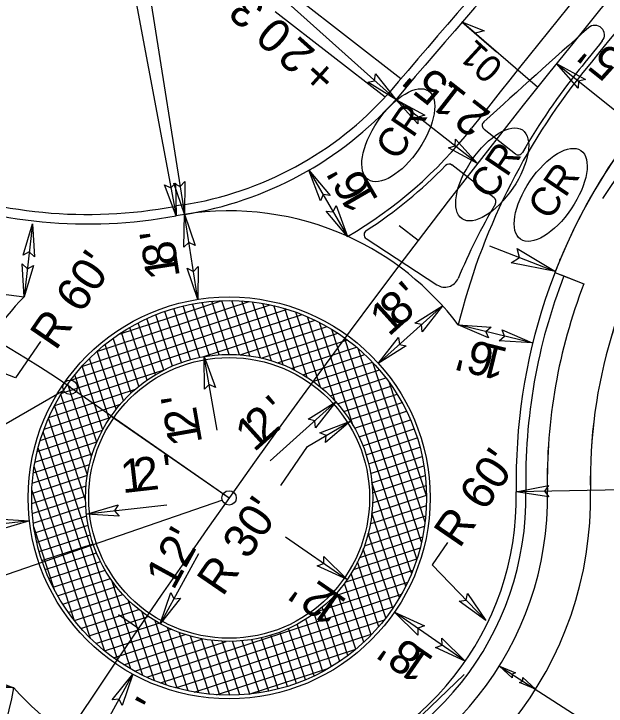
# Model space of a CAD drawing. Extents: x 1975573 to 1977432, y 778300 to 780514.
# Drawn here: x 1976308 to 1976462.7, y 779399.7 to 779580.6 of the extents above; entities that cross this region are included whole.
import ezdxf

# ---------------------------------------------------------------- set-up
doc = ezdxf.new("R2010")
doc.units = 0
for name, color, linetype in [('Default', 7, 'Continuous'), ('Prop Conc 1ft 6in Curb and Gutter', 7, 'Continuous'), ('Prop Conc 2ft 6in Curb and Gutter', 7, 'Continuous'), ('Prop Conc 4in Sidewalk', 7, 'Continuous'), ('Prop Conc 5in Monolithic Keyed In Island', 7, 'Continuous'), ('Prop Conc Curb 8in x 18in', 7, 'Continuous'), ('Prop Conc Drive Radius Type', 7, 'Continuous'), ('Prop Dimension', 7, 'Continuous'), ('Prop Dimension Text', 7, 'Continuous'), ('Prop EOT', 7, 'Continuous'), ('Prop Horizontal Alignment', 7, 'Continuous'), ('Prop Horizontal Alignment Station Label', 7, 'Continuous'), ('Prop Horizontal Alignment Tick Small', 7, 'Continuous'), ('Prop Lane Lines', 7, 'Continuous'), ('Prop Superelevation  Arrow CELL', 7, 'Continuous'), ('Prop Superelevation Label', 7, 'Continuous'), ('Prop Terminator CELL', 7, 'Continuous'), ('Prop WCC CELL', 7, 'Continuous'), ('Typical Terminator CELL', 7, 'Continuous')]:
    doc.layers.add(name, color=color, linetype=linetype)

# ---------------------------------------------------------------- blocks, each defined once
blk = doc.blocks.new('TERMINATOR')
at = {"layer": 'Typical Terminator CELL'}
blk.add_lwpolyline([(-0.4687, 0.0807), (0, 0), (-0.4713, -0.0833), (-0.4114, 0)], close=True, dxfattribs=at)

msp = doc.modelspace()

# ---------------------------------------------------------------- linework, layer by layer
at = {"layer": 'Default'}
for p, q in [((1976329.67, 779492.39), (1976369.49, 779505.41)), ((1976335.46, 779496.92), (1976362.14, 779505.64)), ((1976364.24, 779491.6), (1976359.7, 779505.48)), ((1976366.91, 779491.5), (1976362.28, 779505.64)), ((1976369.63, 779491.2), (1976364.9, 779505.68)), ((1976372.43, 779490.69), (1976367.57, 779505.57)), ((1976325.79, 779488.49), (1976374.92, 779504.56)), ((1976354.17, 779490.24), (1976349.79, 779503.62)), ((1976356.61, 779490.83), (1976352.21, 779504.26)), ((1976359.1, 779491.25), (1976354.67, 779504.79)), ((1976361.64, 779491.51), (1976357.17, 779505.2)), ((1976375.31, 779489.92), (1976370.28, 779505.32)), ((1976378.29, 779488.88), (1976373.04, 779504.92)), ((1976381.38, 779487.44), (1976375.86, 779504.35)), ((1976384.63, 779485.54), (1976378.73, 779503.6)), ((1976320.54, 779481.52), (1976383.28, 779502.03)), ((1976322.86, 779484.91), (1976379.41, 779503.39)), ((1976349.45, 779488.57), (1976345.06, 779501.99)), ((1976351.78, 779489.49), (1976347.41, 779502.86)), ((1976388.09, 779483.03), (1976381.68, 779502.64)), ((1976347.17, 779487.5), (1976342.76, 779501)), ((1976357.63, 779491.02), (1976386.7, 779500.52)), ((1976391.9, 779479.41), (1976384.7, 779501.44)), ((1976342.78, 779484.86), (1976338.26, 779498.67)), ((1976344.95, 779486.26), (1976340.49, 779499.9)), ((1976367.12, 779491.49), (1976389.78, 779498.9)), ((1976396.64, 779472.96), (1976387.81, 779499.97)), ((1976411.87, 779434.42), (1976391.03, 779498.16)), ((1976340.67, 779483.27), (1976336.07, 779497.32)), ((1976372.61, 779490.65), (1976392.58, 779497.18)), ((1976338.62, 779481.49), (1976333.92, 779495.84)), ((1976376.84, 779489.4), (1976395.13, 779495.39)), ((1976413.26, 779438.2), (1976394.39, 779495.93)), ((1976336.64, 779479.49), (1976331.82, 779494.23)), ((1976380.39, 779487.93), (1976397.48, 779493.52)), ((1976414.47, 779442.56), (1976397.94, 779493.13)), ((1976334.74, 779477.26), (1976329.76, 779492.48)), ((1976383.45, 779486.3), (1976399.63, 779491.6)), ((1976332.93, 779474.76), (1976327.76, 779490.58)), ((1976386.11, 779484.54), (1976401.62, 779489.61)), ((1976415.39, 779447.79), (1976401.77, 779489.46)), ((1976318.66, 779478.28), (1976347.77, 779487.79)), ((1976331.22, 779471.93), (1976325.8, 779488.51)), ((1976388.48, 779482.69), (1976403.45, 779487.58)), ((1976329.67, 779468.64), (1976323.9, 779486.27)), ((1976390.59, 779480.75), (1976405.13, 779485.5)), ((1976328.29, 779464.81), (1976322.07, 779483.82)), ((1976415.78, 779454.65), (1976406.13, 779484.15)), ((1976317.14, 779475.15), (1976339.76, 779482.54)), ((1976392.48, 779478.73), (1976406.68, 779483.38)), ((1976327.21, 779460.05), (1976320.31, 779481.16)), ((1976394.16, 779476.66), (1976408.09, 779481.21)), ((1976315.9, 779472.11), (1976335.85, 779478.63)), ((1976395.66, 779474.52), (1976409.38, 779479)), ((1976326.73, 779453.5), (1976318.64, 779478.23)), ((1976396.98, 779472.32), (1976410.55, 779476.75)), ((1976314.9, 779469.15), (1976333.19, 779475.13)), ((1976338.51, 779409.42), (1976317.07, 779474.99)), ((1976398.14, 779470.07), (1976411.6, 779474.47)), ((1976314.11, 779466.26), (1976331.18, 779471.85)), ((1976335.2, 779411.5), (1976315.62, 779471.36)), ((1976399.14, 779467.76), (1976412.53, 779472.14)), ((1976399.98, 779465.41), (1976413.35, 779469.78)), ((1976313.5, 779463.44), (1976329.71, 779468.73)), ((1976313.07, 779460.67), (1976328.59, 779465.74)), ((1976331.72, 779414.09), (1976314.35, 779467.22)), ((1976400.64, 779462.99), (1976414.05, 779467.38)), ((1976401.15, 779460.53), (1976414.63, 779464.94)), ((1976312.8, 779457.95), (1976327.77, 779462.84)), ((1976328, 779417.42), (1976313.32, 779462.34)), ((1976401.5, 779458.01), (1976415.1, 779462.46)), ((1976312.67, 779455.27), (1976327.21, 779460.03)), ((1976401.67, 779455.44), (1976415.45, 779459.94)), ((1976312.68, 779452.65), (1976326.87, 779457.29)), ((1976410.34, 779431.06), (1976401.48, 779458.16)), ((1976401.67, 779452.81), (1976415.68, 779457.39)), ((1976323.87, 779422.02), (1976312.7, 779456.18)), ((1976401.48, 779450.12), (1976415.78, 779454.79)), ((1976312.82, 779450.06), (1976326.74, 779454.61)), ((1976313.08, 779447.52), (1976326.8, 779452)), ((1976401.08, 779447.36), (1976415.74, 779452.15)), ((1976313.47, 779445.01), (1976327.04, 779449.45)), ((1976400.45, 779444.52), (1976415.57, 779449.46)), ((1976408.7, 779428.04), (1976401.48, 779450.11)), ((1976318.6, 779430.08), (1976313.21, 779446.56)), ((1976313.97, 779442.55), (1976327.43, 779446.95)), ((1976399.55, 779441.59), (1976415.25, 779446.73)), ((1976314.59, 779440.12), (1976328, 779444.5)), ((1976398.34, 779438.57), (1976414.77, 779443.94)), ((1976406.97, 779425.29), (1976400.55, 779444.92)), ((1976315.33, 779437.73), (1976328.71, 779442.11)), ((1976396.68, 779435.4), (1976414.11, 779441.09)), ((1976405.16, 779422.77), (1976399.26, 779440.81)), ((1976316.18, 779435.38), (1976329.59, 779439.76)), ((1976317.15, 779433.07), (1976330.63, 779437.47)), ((1976394.53, 779432.06), (1976413.26, 779438.18)), ((1976403.28, 779420.46), (1976397.75, 779437.39)), ((1976318.23, 779430.79), (1976331.82, 779435.23)), ((1976391.52, 779428.45), (1976412.19, 779435.2)), ((1976319.44, 779428.55), (1976333.2, 779433.05)), ((1976401.35, 779418.34), (1976396.1, 779434.4)), ((1976341.69, 779407.74), (1976333.59, 779432.52)), ((1976386.97, 779424.33), (1976410.86, 779432.14)), ((1976399.36, 779416.38), (1976394.32, 779431.77)), ((1976320.77, 779426.36), (1976334.75, 779430.93)), ((1976397.31, 779414.58), (1976392.45, 779429.44)), ((1976322.22, 779424.2), (1976336.5, 779428.87)), ((1976342.74, 779407.24), (1976409.24, 779428.98)), ((1976323.81, 779422.09), (1976338.45, 779426.88)), ((1976344.77, 779406.37), (1976337.87, 779427.47)), ((1976395.23, 779412.92), (1976390.5, 779427.38)), ((1976325.53, 779420.03), (1976340.64, 779424.96)), ((1976347.76, 779405.25), (1976341.54, 779424.29)), ((1976346.29, 779405.77), (1976407.24, 779425.7)), ((1976393.09, 779411.4), (1976388.48, 779425.53)), ((1976327.41, 779418.01), (1976343.1, 779423.14)), ((1976350.33, 779404.46), (1976404.76, 779422.25)), ((1976388.7, 779408.74), (1976384.23, 779422.41)), ((1976390.92, 779410.01), (1976386.39, 779423.88)), ((1976329.45, 779416.04), (1976345.9, 779421.42)), ((1976350.68, 779404.37), (1976344.92, 779421.97)), ((1976386.45, 779407.59), (1976382.02, 779421.12)), ((1976331.66, 779414.14), (1976349.08, 779419.83)), ((1976353.54, 779403.67), (1976348.11, 779420.27)), ((1976356.33, 779403.16), (1976351.16, 779418.99)), ((1976355.06, 779403.38), (1976401.58, 779418.59)), ((1976381.82, 779405.65), (1976377.44, 779419.05)), ((1976384.15, 779406.57), (1976379.76, 779420.01)), ((1976334.06, 779412.29), (1976352.78, 779418.41)), ((1976336.69, 779410.52), (1976357.34, 779417.27)), ((1976359.08, 779402.81), (1976354.1, 779418.03)), ((1976361.77, 779402.61), (1976356.96, 779417.35)), ((1976364.42, 779402.56), (1976359.73, 779416.91)), ((1976372.11, 779403.16), (1976367.66, 779416.8)), ((1976374.6, 779403.61), (1976370.18, 779417.12)), ((1976377.04, 779404.18), (1976372.65, 779417.6)), ((1976379.45, 779404.86), (1976375.07, 779418.25)), ((1976339.56, 779408.83), (1976363.41, 779416.63)), ((1976367.03, 779402.63), (1976362.43, 779416.68)), ((1976369.59, 779402.84), (1976365.07, 779416.65)), ((1976360.92, 779402.66), (1976397.28, 779414.55)), ((1976369.45, 779402.82), (1976390.29, 779409.64))]:
    msp.add_line(p, q, dxfattribs=at)
msp.add_circle((1976364.22, 779454.12), 37.5, dxfattribs=at)
at = {"layer": 'Prop Conc 1ft 6in Curb and Gutter'}
msp.add_circle((1976364.22, 779454.12), 51.56, dxfattribs=at)
at = {"layer": 'Prop Conc 2ft 6in Curb and Gutter'}
for centre, radius, start, end in [((1978239.96, 778006.13), 2403.74, 136.72119, 139.7323), ((1976337.97, 779620.81), 91.25, 278.9494, 318.0674), ((1976327.31, 779650.68), 122.5, 248.3898, 280.6337), ((1976364.22, 779454.12), 77.5, 98.9494, 100.6337), ((1976589.17, 779458.81), 147.5, 158.8164, 181.1936), ((1976364.22, 779454.12), 77.5, 281.7976, 1.1936)]:
    msp.add_arc(centre, radius, start, end, dxfattribs=at)
at = {"layer": 'Prop Conc 4in Sidewalk'}
for p, q in [((1976409.06, 779563.62), (1976380.92, 779585.56)), ((1976376.28, 779581.25), (1976404.98, 779558.88)), ((1976449.31, 779513.01), (1976456.88, 779510.07)), ((1976449.31, 779513.01), (1976456.88, 779510.07)), ((1976449.31, 779513.01), (1976451.64, 779512.11)), ((1976451.64, 779512.11), (1976456.88, 779510.07))]:
    msp.add_line(p, q, dxfattribs=at)
for centre, radius, start, end in [((1976589.17, 779458.81), 150, 142.1787, 158.8164), ((1976589.17, 779458.81), 150, 142.1787, 158.8164), ((1976589.17, 779458.81), 130.63, 145.3825, 181.1936), ((1976589.17, 779458.81), 130.62, 145.3825, 181.1936), ((1976589.17, 779458.81), 141.88, 158.8164, 181.1936), ((1976589.17, 779458.81), 141.87, 158.8164, 181.1936), ((1976589.17, 779458.81), 141.87, 158.8164, 181.1936), ((1976364.22, 779454.12), 83.13, 281.7976, 1.1936), ((1976364.22, 779454.12), 83.12, 281.7976, 1.1936), ((1976364.22, 779454.12), 83.13, 281.7976, 1.1936), ((1976364.22, 779454.12), 94.38, 281.7976, 1.1936), ((1976364.22, 779454.12), 94.38, 281.7976, 1.1936)]:
    msp.add_arc(centre, radius, start, end, dxfattribs=at)
at = {"layer": 'Prop Conc 5in Monolithic Keyed In Island'}
msp.add_line((1976400.03, 779521.91), (1976418.5, 779509.78), dxfattribs=at)
for points in [[(1976430.8, 779550.44), (1976438.98, 779544.02)], [(1976433.43, 779532.56), (1976422.41, 779541.1)], [(1976400.03, 779521.91), (1976418.5, 779509.78)]]:
    msp.add_lwpolyline(points, dxfattribs=at)
for centre, radius, start, end in [((1978056.54, 777773.04), 2410.22, 131.54456, 132.41906), ((1978056.54, 777773.04), 2410.22, 131.54456, 132.41906), ((1976459.73, 779575.08), 2.5, 321.0068, 131.5446), ((1976459.73, 779575.08), 2.5, 321.0068, 131.5446), ((1978303.2, 778082.63), 2369.38, 141.00683, 141.23948), ((1978303.2, 778082.63), 2369.38, 141.00683, 141.23948), ((1976589.17, 779458.81), 171.25, 141.2395, 150.018), ((1976589.17, 779458.81), 171.25, 141.2395, 150.018), ((1976431.57, 779551.42), 1.25, 132.4191, 231.9065), ((1976431.57, 779551.42), 1.25, 132.4191, 231.9065), ((1976439.75, 779545.01), 1.25, 231.9065, 330.018), ((1976439.75, 779545.01), 1.25, 231.9065, 330.018), ((1976337.97, 779620.81), 115, 302.6674, 316.0364), ((1976337.97, 779620.81), 115, 302.6674, 316.0364), ((1976421.64, 779540.11), 1.25, 52.2081, 136.0364), ((1976421.64, 779540.11), 1.25, 52.2081, 136.0364), ((1976432.66, 779531.57), 1.25, 329.792, 52.2081), ((1976432.66, 779531.57), 1.25, 329.792, 52.2081), ((1976580.48, 779445.51), 169.79, 149.792, 157.1435), ((1976580.48, 779445.51), 169.79, 149.792, 157.1435), ((1976400.71, 779522.95), 1.25, 122.6674, 236.722), ((1976400.71, 779522.95), 1.25, 122.6674, 236.722), ((1976420.56, 779512.92), 3.75, 236.722, 337.1435), ((1976420.56, 779512.92), 3.75, 236.722, 337.1435)]:
    msp.add_arc(centre, radius, start, end, dxfattribs=at)
at = {"layer": 'Prop Conc Curb 8in x 18in'}
msp.add_circle((1976364.22, 779454.12), 36.67, dxfattribs=at)
at = {"layer": 'Prop Conc Drive Radius Type'}
for p, q in [((1976475.61, 779553.23), (1976461.7, 779532.36)), ((1976425.61, 779407.97), (1976407.53, 779390.7))]:
    msp.add_line(p, q, dxfattribs=at)
at = {"layer": 'Prop Dimension'}
for p, q in [((1976432.24, 779519.95), (1976449.42, 779513.3)), ((1976450.54, 779516.2), (1976450.68, 779516.56)), ((1976434.79, 779410.19), (1976466.33, 779389.91))]:
    msp.add_line(p, q, dxfattribs=at)
at = {"layer": 'Prop Dimension Text'}
for p, q in [((1976327.31, 779650.68), (1976350.38, 779527.83)), ((1976337.97, 779620.81), (1976352.55, 779528.21)), ((1976337.97, 779620.81), (1976407.71, 779558.17)), ((1976449.69, 779567.6), (1976470.68, 779550.79)), ((1976429.09, 779541.52), (1976407.71, 779558.17)), ((1976385.06, 779539.75), (1976395.11, 779522.46)), ((1976356.05, 779505.98), (1976352.55, 779528.21)), ((1976312.88, 779525.73), (1976310.68, 779506.64)), ((1976403.18, 779489.25), (1976419.92, 779504.34)), ((1976443.35, 779494.59), (1976424.07, 779499.32)), ((1976314.93, 779494.98), (1976308.4, 779485.46)), ((1976361.1, 779471.83), (1976357.73, 779491.05)), ((1976308.4, 779485.46), (1976298.09, 779489.5)), ((1976374.96, 779463.81), (1976392.07, 779479.23)), ((1976333.38, 779475.45), (1976364.22, 779454.12)), ((1976384.66, 779467.52), (1976395.91, 779474.16)), ((1976377.72, 779457.38), (1976384.66, 779467.52)), ((1976589.17, 779458.81), (1976439.2, 779455.68)), ((1976347.97, 779452.26), (1976326.96, 779449.85)), ((1976312.06, 779448.15), (1976289.7, 779445.59)), ((1976378.97, 779443.91), (1976395.06, 779432.79)), ((1976421.25, 779442.45), (1976417.25, 779436.61)), ((1976356.23, 779439.5), (1976346.23, 779421.21)), ((1976417.25, 779436.61), (1976431.23, 779422.07)), ((1976425.9, 779411.46), (1976407.4, 779424.25)), ((1976289.66, 779407.94), (1976308, 779404.47)), ((1976328.24, 779388.31), (1976339.03, 779408.05))]:
    msp.add_line(p, q, dxfattribs=at)
at = {"layer": 'Prop EOT'}
msp.add_circle((1976364.22, 779454.12), 52.5, dxfattribs=at)
for centre, radius, start, end in [((1978239.96, 778006.13), 2401.24, 136.7176, 139.73317), ((1976337.97, 779620.81), 93.75, 278.9494, 318.0674), ((1976589.17, 779458.81), 150, 142.1787, 181.1936), ((1976327.31, 779650.68), 125, 248.3898, 280.6337), ((1976364.22, 779454.12), 75, 98.9494, 100.6337), ((1976364.22, 779454.12), 75, 281.7976, 1.1936)]:
    msp.add_arc(centre, radius, start, end, dxfattribs=at)
at = {"layer": 'Prop Horizontal Alignment'}
msp.add_line((1976322.68, 779483.02), (1976364.22, 779454.12), dxfattribs=at)
msp.add_line((1976322.68, 779483.02), (1976364.22, 779454.12), dxfattribs=at)
for centre, radius, start, end in [((1978303.2, 778082.63), 2375, 135.73946, 152.1381), ((1976179.17, 779276.72), 251.3, 55.1768, 88.8319), ((1976179.17, 779276.72), 251.3, 55.1768, 88.8319), ((1976179.17, 779276.72), 251.3, 55.1768, 88.8319), ((1976179.17, 779276.72), 251.3, 55.1768, 88.8319), ((1976179.17, 779276.72), 251.3, 55.1768, 88.8319)]:
    msp.add_arc(centre, radius, start, end, dxfattribs=at)
at = {"layer": 'Prop Horizontal Alignment Station Label'}
for p, q in [((1976321.01, 779482.16), (1976180.99, 779401.56)), ((1976362.45, 779453.51), (1976212.49, 779401.79))]:
    msp.add_line(p, q, dxfattribs=at)
for centre in [(1976322.68, 779483.02), (1976322.68, 779483.02), (1976364.22, 779454.12)]:
    msp.add_circle(centre, 1.88, dxfattribs=at)
at = {"layer": 'Prop Horizontal Alignment Tick Small'}
for p, q in [((1976413.61, 779521.41), (1976408.64, 779525.2)), ((1976340.54, 779420.01), (1976335.37, 779423.53))]:
    msp.add_line(p, q, dxfattribs=at)
at = {"layer": 'Prop Lane Lines'}
for centre, radius, start, end in [((1978303.2, 778082.63), 2381.88, 135.73946, 141.94983), ((1978303.2, 778082.63), 2368.12, 135.73946, 141.23948), ((1976589.17, 779458.81), 170, 141.2395, 166.2129), ((1976337.97, 779620.81), 113.75, 300.1571, 321.9498), ((1976364.22, 779454.12), 75, 65.6747, 98.9494), ((1976364.22, 779454.12), 75, 37.0615, 65.6747), ((1976327.31, 779650.68), 145, 250.6014, 263.4132), ((1976364.22, 779454.12), 75, 135.5489, 156.1292), ((1976165.52, 779431.37), 145, 330.7648, 349.3113), ((1976364.22, 779454.12), 75, 221.447, 248.5228)]:
    msp.add_arc(centre, radius, start, end, dxfattribs=at)
at = {"layer": 'Prop Superelevation  Arrow CELL'}
msp.add_line((1976424.98, 779578.54), (1976434.06, 779570.69), dxfattribs=at)
msp.add_lwpolyline([(1976424.98, 779578.54), (1976430.83, 779576.13), (1976428.48, 779575.51)], close=True, dxfattribs=at)
at = {"layer": 'Prop Superelevation Label'}
msp.add_line((1976444.77, 779561.44), (1976424.98, 779578.54), dxfattribs=at)
at = {"layer": 'Prop Terminator CELL'}
for points in [[(1976455.37, 779561.19), (1976449.69, 779567.6), (1976457.25, 779563.47), (1976455.47, 779562.97)], [(1976402.4, 779564.88), (1976407.71, 779558.17), (1976400.4, 779562.72), (1976402.2, 779563.11)], [(1976413.48, 779551.84), (1976407.71, 779558.17), (1976415.33, 779554.14), (1976413.55, 779553.62)], [(1976423.33, 779547.85), (1976429.09, 779541.52), (1976421.48, 779545.55), (1976423.25, 779546.07)], [(1976388.05, 779531.73), (1976385.06, 779539.75), (1976390.62, 779533.17), (1976388.79, 779533.35)], [(1976350.25, 779536.39), (1976350.38, 779527.83), (1976347.34, 779535.89), (1976349.01, 779535.11)], [(1976352.67, 779536.77), (1976352.55, 779528.21), (1976349.75, 779536.35), (1976351.4, 779535.52)], [(1976392.13, 779530.49), (1976395.11, 779522.46), (1976389.55, 779529.04), (1976391.39, 779528.86)], [(1976352.43, 779519.64), (1976352.55, 779528.21), (1976355.35, 779520.06), (1976353.7, 779520.89)], [(1976310.47, 779517.52), (1976312.88, 779525.73), (1976313.4, 779517.13), (1976312.03, 779518.37)], [(1976313.09, 779514.86), (1976310.68, 779506.64), (1976310.16, 779515.24), (1976311.53, 779514)], [(1976356.17, 779514.54), (1976356.05, 779505.98), (1976353.25, 779514.13), (1976354.9, 779513.3)], [(1976412.68, 779499.77), (1976419.92, 779504.34), (1976414.62, 779497.55), (1976414.42, 779499.38)], [(1976431.92, 779495.9), (1976424.07, 779499.32), (1976432.66, 779498.75), (1976431.26, 779497.55)], [(1976435.5, 779498.01), (1976443.35, 779494.59), (1976434.75, 779495.15), (1976436.15, 779496.35)], [(1976410.42, 779493.82), (1976403.18, 779489.25), (1976408.48, 779496.05), (1976408.68, 779494.21)], [(1976357.76, 779482.49), (1976357.73, 779491.05), (1976360.67, 779482.96), (1976359.01, 779483.76)], [(1976384.83, 779474.66), (1976392.07, 779479.23), (1976386.77, 779472.44), (1976386.57, 779474.27)], [(1976387.91, 779471.12), (1976395.91, 779474.16), (1976389.37, 779468.56), (1976389.53, 779470.4)], [(1976447.67, 779454.4), (1976439.2, 779455.68), (1976447.65, 779457.36), (1976446.61, 779455.84)], [(1976335.51, 779449.37), (1976326.96, 779449.85), (1976335.22, 779452.31), (1976334.32, 779450.7)], [(1976303.51, 779448.63), (1976312.06, 779448.15), (1976303.8, 779445.69), (1976304.7, 779447.3)], [(1976388.95, 779438.78), (1976395.06, 779432.79), (1976387.23, 779436.38), (1976388.97, 779437)], [(1976351.55, 779427.92), (1976346.23, 779421.21), (1976348.98, 779429.38), (1976349.78, 779427.71)], [(1976426.43, 779429.16), (1976431.23, 779422.07), (1976424.27, 779427.15), (1976426.09, 779427.41)], [(1976413.51, 779418.26), (1976407.4, 779424.25), (1976415.23, 779420.66), (1976413.49, 779420.04)], [(1976419.79, 779417.45), (1976425.9, 779411.46), (1976418.07, 779415.05), (1976419.81, 779415.67)], [(1976438.15, 779407.1), (1976434.79, 779410.19), (1976439.03, 779408.42), (1976438.11, 779408.05)], [(1976333.71, 779401.35), (1976339.03, 779408.05), (1976336.28, 779399.89), (1976335.48, 779401.55)], [(1976299.98, 779407.47), (1976308, 779404.47), (1976299.39, 779404.57), (1976300.72, 779405.85)], [(1976440.88, 779407.19), (1976444.25, 779404.11), (1976440.01, 779405.88), (1976440.93, 779406.24)]]:
    msp.add_lwpolyline(points, close=True, dxfattribs=at)
at = {"layer": 'Prop WCC CELL'}
for centre in [(1976408.4, 779548.87), (1976432.92, 779538.65), (1976448.19, 779533.29)]:
    msp.add_ellipse(centre, major_axis=(7.87, 11.6), ratio=0.462467, dxfattribs=at)

# ---------------------------------------------------------------- block references
at = {"layer": 'Prop Dimension', "xscale": 24.499999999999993, "yscale": 24.499999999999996, "rotation": -21.1552981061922}
msp.add_blockref('TERMINATOR', (1976449.42, 779513.3), dxfattribs=at)

# ---------------------------------------------------------------- texts
at = {"layer": 'Prop Dimension Text'}
for s, height, rotation, p in [('3', 8.75, 138.0674, (1976374.11, 779582.47)), ('0', 8.75, 138.0674, (1976381.28, 779576.02)), ('2', 8.75, 138.0674, (1976387.13, 779570.77)), ('5', 8.75, 141.2995, (1976467.84, 779569.27)), ("'", 8.75, 141.2995, (1976461.92, 779574.01)), ('+', 8.75, 138.0674, (1976393.28, 779565.25)), ('5', 8.75, 142.1012, (1976422.16, 779563.01)), ("'", 8.75, 142.1012, (1976416.18, 779567.67)), ('1', 8.75, 142.1012, (1976426.73, 779559.46)), ('.', 8.75, 142.1012, (1976424.01, 779561.58)), ('2', 8.75, 142.1012, (1976432.93, 779554.64)), ("'", 8.75, 120.1571, (1976398.14, 779541.07)), ('6', 8.75, 120.1571, (1976401.67, 779534.99)), ('1', 8.75, 120.1571, (1976403.4, 779532.01)), ('DETAIL OF ROUNDABOUT @ -Y2-', 25, 55.5983, (1976426.44, 779079.33)), ("'", 8.75, 98.9494, (1976349.71, 779522.57)), ('8', 8.75, 98.9494, (1976350.84, 779515.36)), ("R 60'", 8.75, 55.5805, (1976318.93, 779492.36)), ('1', 8.75, 98.9494, (1976351.38, 779511.96)), ("'", 8.75, 42.0418, (1976413.89, 779503.28)), ('8', 8.75, 42.0418, (1976408.46, 779498.39)), ('1', 8.75, 42.0418, (1976405.9, 779496.08)), ('6', 8.75, 166.2129, (1976434.05, 779493.94)), ('1', 8.75, 166.2129, (1976437.4, 779493.12)), ("'", 8.75, 166.2129, (1976427.23, 779495.61)), ("'", 8.75, 99.9679, (1976355.28, 779479.69)), ("'", 8.75, 42.0418, (1976379.12, 779473.45)), ('2', 8.75, 99.9679, (1976356.64, 779471.95)), ('2', 8.75, 42.0418, (1976373.29, 779468.19)), ('1', 8.75, 42.0418, (1976370.73, 779465.88)), ('1', 8.75, 99.9679, (1976357.24, 779468.56)), ("R 60'", 8.75, 55.5805, (1976424.36, 779440.69)), ('1', 8.75, 6.5318, (1976336.36, 779455.33)), ('2', 8.75, 6.5318, (1976339.78, 779455.72)), ("'", 8.75, 6.5318, (1976347.58, 779456.62)), ("R 30'", 8.75, 55.5805, (1976362.5, 779428.09)), ("12'", 8.75, 61.3342, (1976349.66, 779429.75)), ('2', 8.75, 145.3305, (1976392.53, 779429.22)), ("'", 8.75, 145.3305, (1976386.07, 779433.69)), ('1', 8.75, 145.3305, (1976395.36, 779427.26)), ('8', 8.75, 145.3305, (1976415.22, 779414.18)), ('1', 8.75, 145.3305, (1976418.06, 779412.23)), ("'", 8.75, 145.3305, (1976409.22, 779418.34)), ("'", 8.75, 61.3342, (1976347.05, 779396.62))]:
    msp.add_text(s, height=height, rotation=rotation, dxfattribs=at).set_placement(p)
at = {"layer": 'Prop Superelevation Label'}
msp.add_text('01', height=7, rotation=137.4103, dxfattribs=at).set_placement((1976436.18, 779567.14))
at = {"layer": 'Prop WCC CELL'}
for p in [(1976408.15, 779541.92), (1976432.66, 779531.7), (1976447.93, 779526.34)]:
    msp.add_text('CR', height=7.5, rotation=55.8441, dxfattribs=at).set_placement(p)

doc.saveas('drawing.dxf')
